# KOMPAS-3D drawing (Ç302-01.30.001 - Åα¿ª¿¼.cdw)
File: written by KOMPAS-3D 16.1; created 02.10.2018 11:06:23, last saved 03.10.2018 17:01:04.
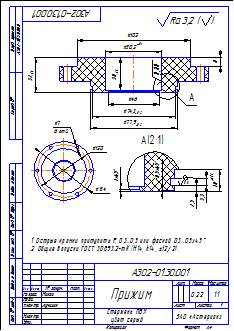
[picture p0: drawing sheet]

Sheet 1: A4, portrait

Title block, sheet 1: name: Прижим; designation: А302-01.30.001; mass: 0,22; scale: 1:1; sheets: 1; organisation: ЗАО «Астерион»; sheet format: A4; stored path: \\192.168.87.28\Konstructor_doc\Мембранные насосы\Мембранный электропривод\А302-00.00.000 - ASTRA-302 (МЭ200)\3Д ПВХ\А302-01.30.001 - Прижим.cdw; drawn by: Милов; technical control: Лучихин

Views: Вид 1, Местный разрез 1, Вид:1, Проекционный вид 2, Выносной элемент 3, Проекционный вид 4, Выносной элемент А, Выносной элемент
Referenced files in \\192.168.87.28\Konstructor_doc\Мембранные насосы\Мембранный электропривод\А302-00.00.000 - ASTRA-302 (МЭ200)\3Д ПВХ\: А302-01.30.001 - Прижим.m3d
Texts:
  Стержень ПВХ
  цвет серый
  Острые кромки притупить R 0,3...0,5 или фаской 0,3...0,5х45 .
  Общие допуски ГОСТ 30893.2-mK (H14, h14,  t2/2).
  Ra 3,2
  Ra 3,2 ( )
Dimensions and other numbers on the sheet: 46; 50,2; 8; 30; 32; 0,80; 102; 74,3; 77,9; 1; 0,5; 2,5; 3,3; 10; 0,8; 134; 120; 7; 6 отв.; 1:1; 0,22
